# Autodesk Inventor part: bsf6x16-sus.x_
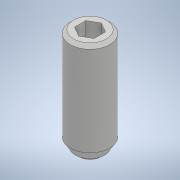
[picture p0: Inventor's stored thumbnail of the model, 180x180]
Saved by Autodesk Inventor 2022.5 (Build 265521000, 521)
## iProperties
Created: 2020-01
Part Number: bsf6x16-sus.x_
Material: 一般
Document SubType Name: Modeling
Designer: ImaoCorp
Density: 1 g/cm^3
Appearance: 既定
Sending System: SOLIDWORKS 2018-2018316
MC: AMD64
MC_MODEL: Intel64 Family 6 Model 60 Stepping 3, GenuineIntel
OS: Windows_NT
FRU: Parasolid Version 30.0, build 310,  6- 8-2018
FORMAT: text
GUISE: transmit
KEY: bsf6x16-sus
FILE: bsf6x16-sus.x_t
DATE: Thu Jan 23 16:48:30 2020
Author: ImaoCorp
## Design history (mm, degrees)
feature "Base1"
node "ソリッド1"
